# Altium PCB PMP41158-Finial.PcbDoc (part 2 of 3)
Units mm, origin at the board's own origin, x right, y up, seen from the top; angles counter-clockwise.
Board outline 125.73 x 87.63 mm, 6 copper layers (Top Layer, Layer 2, Layer 3, Layer 4, Layer 5, Bottom Layer), stack 1.999 mm thick; 200 components, 69 nets, 525 pads, 780 vias.
Unrouted connection lines stored in the file: 16.
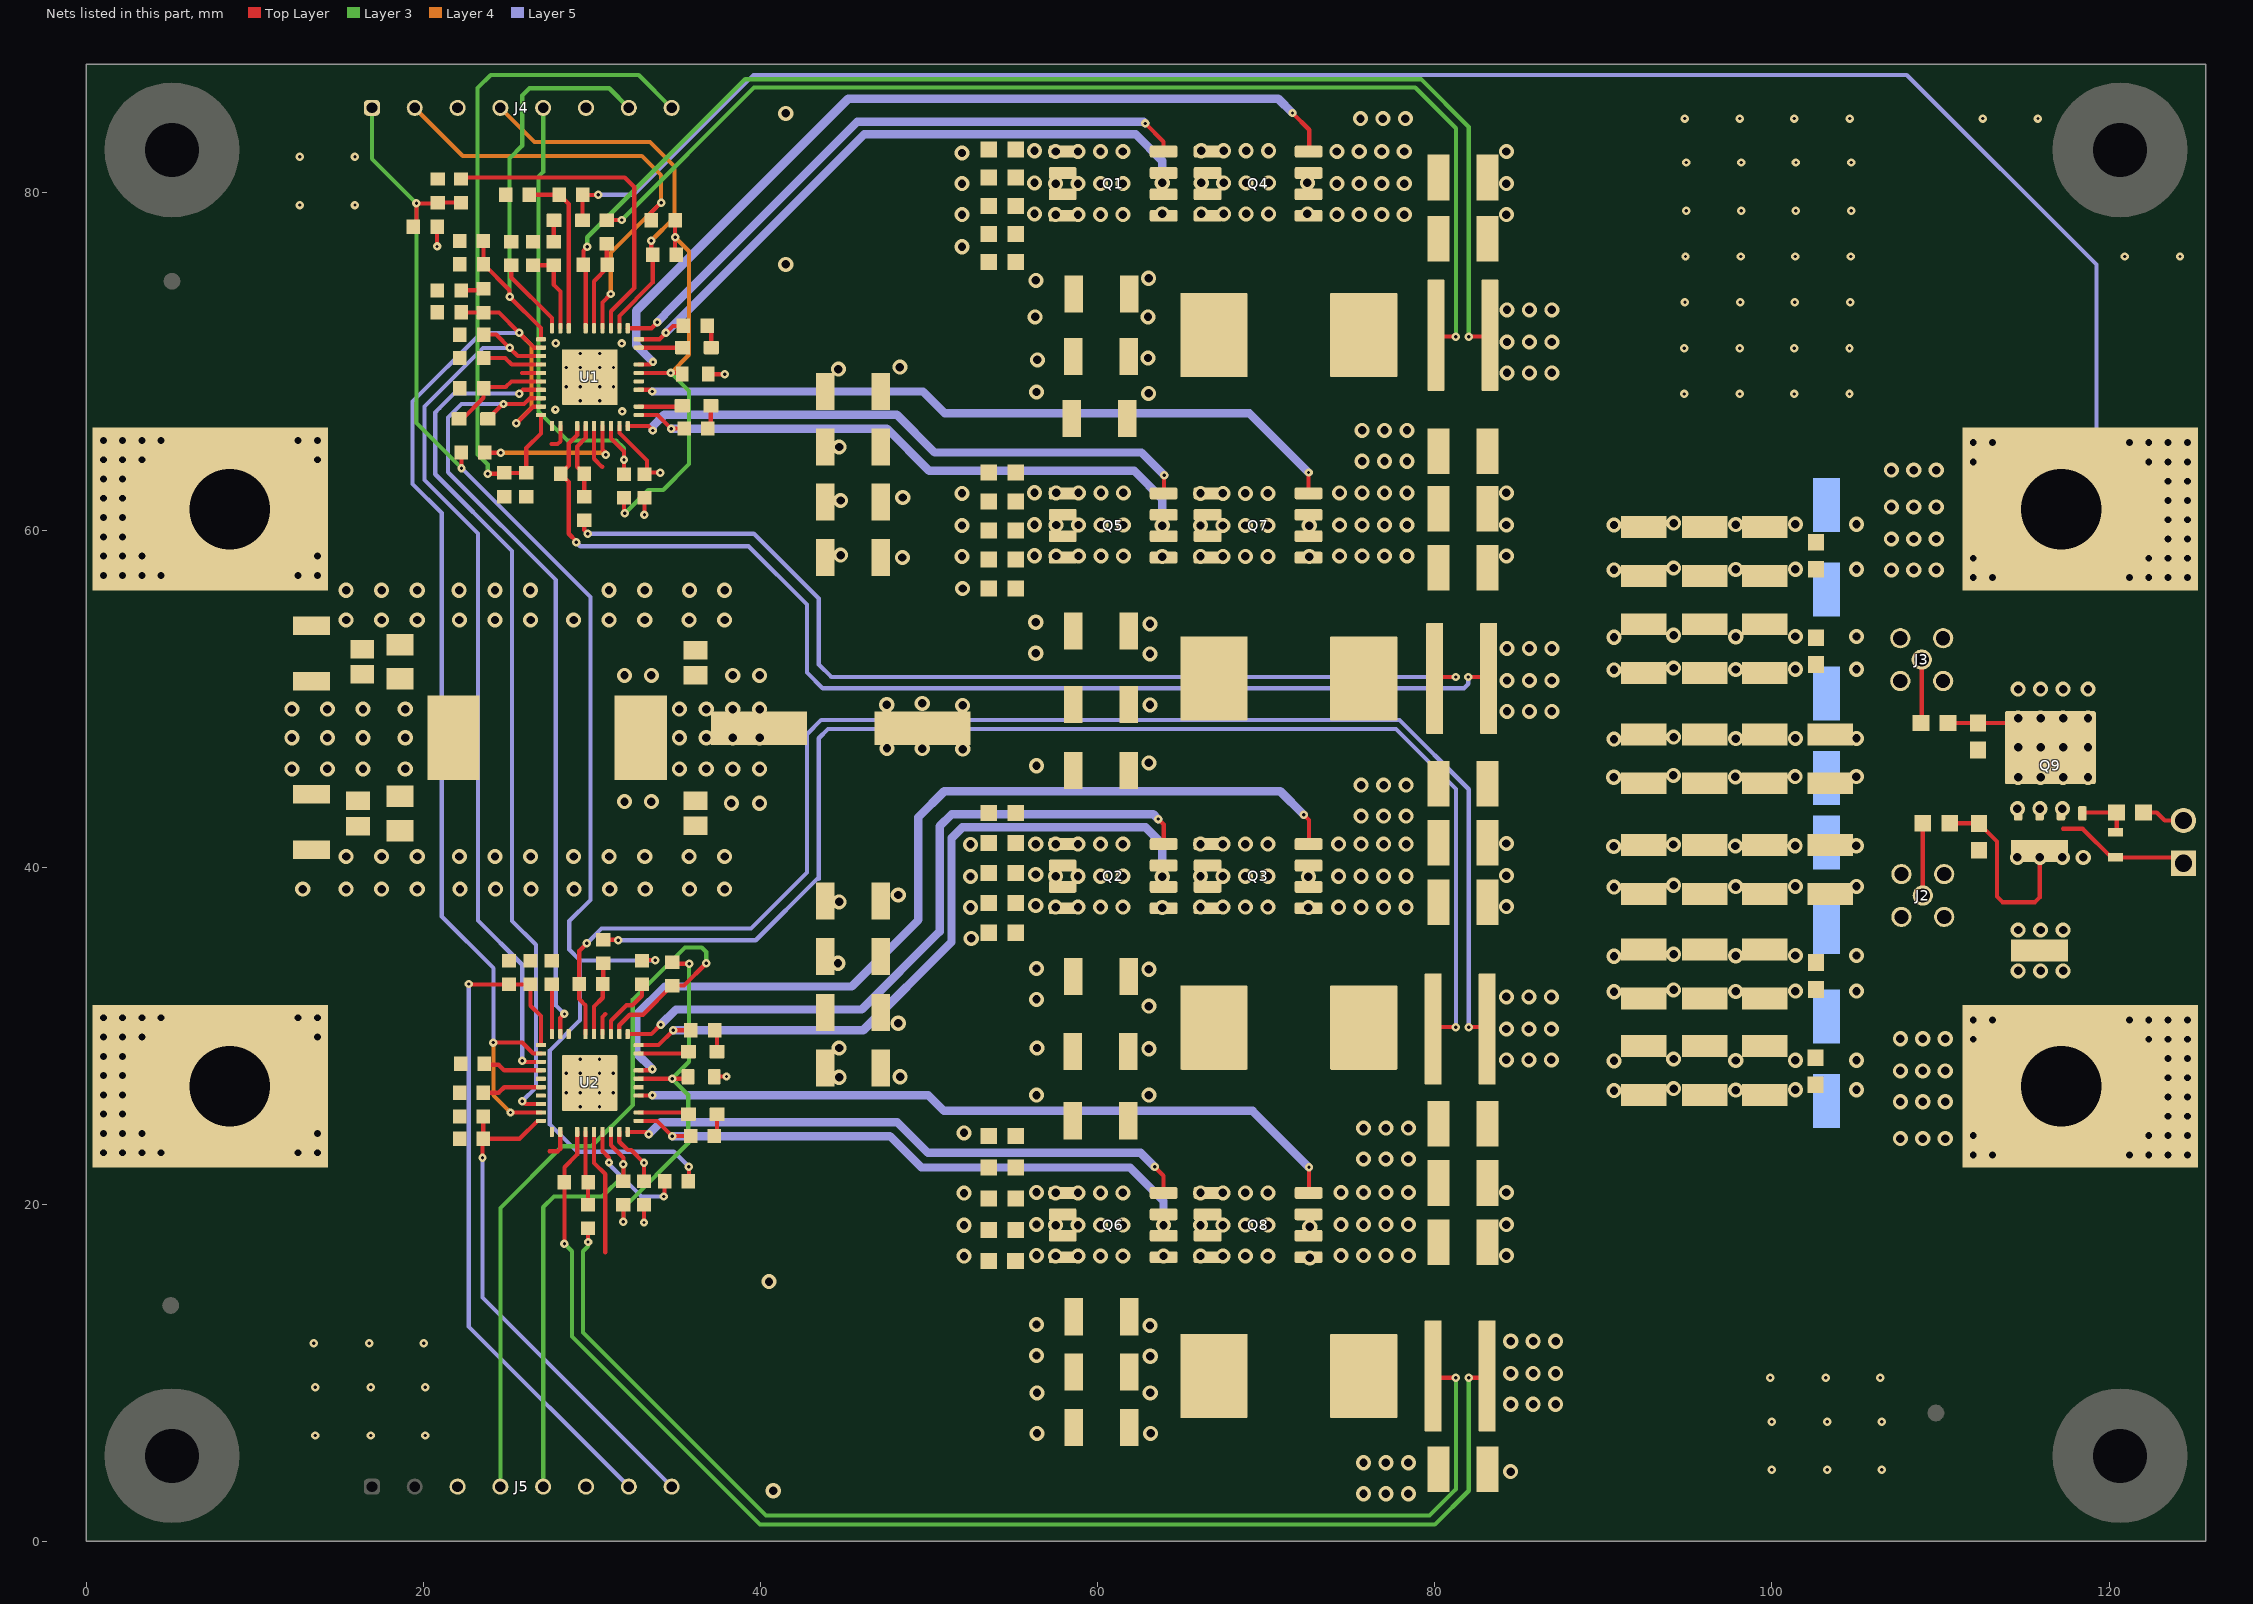
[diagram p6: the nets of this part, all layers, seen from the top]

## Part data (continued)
R46: library part CMP-0025686-1, "RES, 10.0 k, 0.1%, 0.1 W, AEC-Q200 Grade 1, 0603", Manufacturer=Vishay-Dale, Power_W=100mW, Supplier Part Number 1=TNP10.0KAACT-ND, TempCo="25 ppm/C", Tolerance_%=0.1%, Value2=0.1W, Value_Code=10k0, ValueDisplayed=10.0k
R47 R48: library part CMP-0022447-4, "RES, 49.9 k, 1%, 0.1 W, AEC-Q200 Grade 0, 0603", Manufacturer=Vishay-Dale, Power_W=100mW, Supplier Part Number 1=541-49.9KHCT-ND, TempCo="100 ppm/C", Tolerance_%=1%, Value2=0.1W, Value_Code=49k9, ValueDisplayed=49.9k
R49: library part CMP-0015418-2, "RES, 0.01, 1%, 3 W, 2512", Manufacturer=Bourns, Power_W=3W, Supplier Part Number 1=CRA2512-FZ-R010ELFCT-ND, TempCo="75 ppm/C", Tolerance_%=1%, Value_Code=R010, ValueDisplayed=0.01
T1 T2 T3 T4: library part CMP-0055442-1, "Terminal 50A Lug", Manufacturer=Panduit, Supplier Part Number 1=CB35-36-CY-ND, Voltage_V=600V
U1 U2: library part CMP-0122321-1, "Automotive, 4-V to 80-V, Functional Safety-Compliant, Dual Synchronous Buck Controller With Low IQ", Manufacturer="Texas Instruments", Max Supply Voltage=80V, Min Supply Voltage=4V, Nominal Supply Current=130uA, Operating Temperature Range="-40°C to +150°C", Output Voltage=0.8-60V, Switching Frequency=100-2200kHz
ZZ1: library part CMP-0003616-3
ZZ2: library part CMP-0077236-1
ZZ3: library part CMP-0077237-1
ZZ4: library part CMP-0077238-1

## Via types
v1: diameter 0.9, hole 0.5, Top Layer to Bottom Layer, 508 vias
v2: diameter 0.5, hole 0.2, Top Layer to Bottom Layer, 136 vias
v3: diameter 0.813, hole 0.406, Top Layer to Bottom Layer, 112 vias
v4: diameter 0.5, hole 0.2, Top Layer to Bottom Layer, tented both sides, 24 vias

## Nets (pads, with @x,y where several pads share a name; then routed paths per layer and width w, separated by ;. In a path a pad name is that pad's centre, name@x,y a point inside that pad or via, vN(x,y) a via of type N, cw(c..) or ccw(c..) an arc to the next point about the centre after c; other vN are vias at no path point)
EN1_1: R30.2 U1.20 | length 19.5
  Top Layer w0.25: R30.2@22.243,80.675 22.478,80.91 31.943,80.91 32.506,80.347 32.506,74.363 31.122,72.98 U1.20@31.122,71.973
EN1_2: R32.2 U2.20 | length 3.9
  Top Layer w0.25: U2.20@31.117,30.098 31.117,30.887 32.038,31.808 32.392,31.808 32.96,32.376 R32.2@32.96,33.044
EN2_1: R31.2 U1.6 | length 9
  Top Layer w0.25: R31.2@23.637,64.607 23.652,64.593 v2(24.579,64.593) ; U1.6@30.622,66.173 30.622,64.787 30.816,64.593 v2(30.816,64.46)
  Layer 4 w0.25: v2(24.579,64.593) 30.683,64.593 v2(30.816,64.46)
EN2_2: R33.2 U2.6 | length 7.1
  Top Layer w0.25: U2.6@30.617,24.298 30.617,23.154 31.006,22.765 v2@31.006,22.38 ; v2(34.26,20.463) 34.304,20.507 R33.2@34.304,21.378
  Layer 5 w0.25: v2@31.006,22.38 32.924,20.463 v2(34.26,20.463)
  other v2: 31.006,22.48
GND: C1.2 C2.2 C3.2 C4.2 C5.2 C6.2 C7.2 C8.2 C9.2 C10.2 C11.2 C12.2 C13.2 C14.2 C15.2 C16.2 C17.2 C18.2 C19.2 C20.2 C21.2 C22.2 C23.2 C24.2 C25.2 C26.2 C27.2 C28.2 C29.2 C30.2 C31.2 C32.2 C33.2 C34.2 C39.1 C40.1 C42.2 C43.2 C47.2 C49.2 C50.2 C51.2 C52.2 C53.2 C54.2 C55.2 C56.2 C57.2 C58.2 C59.2 C60.2 C61.2 C62.2 C63.2 C64.2 C65.2 C66.2 C67.2 C68.2 C69.2 C70.2 C71.2 C72.2 C73.2 C74.2 C77.2 C78.2 C79.2 C80.2 C81.2 C83.2 C84.2 C85.2 C86.2 C87.2 C88.2 C89.2 C90.2 C91.2 C92.2 C93.2 C94.2 C95.2 C96.2 C97.2 C98.2 C99.2 C100.2 C101.2 C102.2 C103.2 C104.2 C105.2 C106.2 C107.2 J2.2 J2.3 J2.4 J2.5 J3.2 J3.3 J3.4 J3.5 Q3.1 Q3.2 Q3.3 Q4.1 Q4.2 Q4.3 Q7.1 Q7.2 Q7.3 Q8.1 Q8.2 Q8.3 R49.1 T2.1 T4.1 U1.13 U1.37 U2.13 U2.37 | length 3.9
  Top Layer w0.25: v2(33.084,18.922) C43.2@33.084,19.968 ; v2(33.109,60.906) C42.2@33.109,61.916 ; C39.1@36.959,69.323 C39.1@36.9,69.264 36.926,69.239 v2(37.867,69.239) ; C40.1@37.247,27.568 37.263,27.584 v2(37.979,27.584)
  other v1: 75.768,2.831 77.101,2.831 78.433,2.831 40.75,3.012 75.768,4.666 77.101,4.666 78.433,4.666 63.137,6.413 63.118,8.809 63.118,10.991 63.101,12.809 40.5,15.414 72.584,16.824 52.067,16.925 74.435,16.959 75.768,16.959 77.101,16.959 78.433,16.959 72.584,18.659 52.067,18.76 74.435,18.794 75.768,18.794 77.101,18.794 78.433,18.794 52.067,20.665 74.435,20.699 75.768,20.699 77.101,20.699 78.433,20.699 75.768,22.688 77.101,22.688 78.433,22.688 107.617,23.901 108.95,23.901 110.283,23.901 52.067,24.239 75.768,24.523 77.101,24.523 78.433,24.523 107.617,26.082 108.95,26.082 110.283,26.082 63.037,26.48 44.656,27.537 107.617,27.917 108.95,27.917 110.283,27.917 90.63,28.507 97.849,28.534 101.395,28.55 105.015,28.55 94.168,28.62 63.037,29.233 44.656,29.275 107.617,29.822 108.95,29.822 110.283,29.822 63.037,31.757 90.63,32.608 97.849,32.635 101.395,32.651 105.015,32.651 94.168,32.722 114.606,33.851 115.939,33.851 117.272,33.851 63.037,33.949 44.591,34.3 52.5,35.779 114.606,36.276 115.939,36.276 117.272,36.276 72.502,37.602 52.452,37.615 74.294,37.627 75.627,37.627 76.96,37.627 78.292,37.627 44.656,37.941 12.841,38.697 15.409,38.697 17.519,38.697 19.629,38.697 22.167,38.697 24.277,38.697 26.387,38.697 28.937,38.697 31.047,38.697 33.157,38.697 35.791,38.697 37.867,38.697 52.452,39.45 72.502,39.437 74.294,39.462 75.627,39.462 76.96,39.462 78.292,39.462 15.409,40.634 17.519,40.634 19.629,40.634 22.134,40.634 24.244,40.634 26.354,40.634 28.904,40.634 31.014,40.634 33.124,40.634 35.757,40.634 37.867,40.634 90.612,41.232 97.831,41.259 101.377,41.275 104.997,41.275 52.452,41.355 94.15,41.346 74.294,41.367 75.627,41.367 76.96,41.367 78.292,41.367 75.627,43.034 76.96,43.034 78.292,43.034 75.627,44.869 76.96,44.869 78.292,44.869 90.612,45.334 97.831,45.361 101.377,45.377 104.997,45.377 94.15,45.447 63.037,46.186 51.993,47.006 47.5,47.052 49.589,47.034 51.981,49.596 47.489,49.642 63.101,49.629 49.589,49.715 63.101,52.651 90.63,53.643 97.849,53.67 101.395,53.686 105.015,53.686 94.168,53.756 63.101,54.433 15.409,54.666 17.519,54.666 19.629,54.666 22.134,54.666 24.244,54.666 26.354,54.666 28.904,54.666 31.014,54.666 33.124,54.666 35.757,54.666 37.867,54.666 15.409,56.434 17.519,56.434 19.629,56.434 22.116,56.434 24.244,56.434 26.347,56.434 31.006,56.434 33.124,56.434 35.791,56.434 37.866,56.434 51.981,56.534 90.63,57.637 97.849,57.664 101.395,57.68 105.015,57.68 94.168,57.75 72.55,58.427 51.949,58.436 74.35,58.464 75.682,58.464 77.015,58.464 78.348,58.464 44.749,58.518 51.949,60.271 72.55,60.262 74.35,60.299 75.682,60.299 77.015,60.299 78.348,60.299 44.749,61.754 51.949,62.176 74.35,62.204 75.682,62.204 77.015,62.204 78.348,62.204 75.682,64.082 77.015,64.082 78.348,64.082 44.656,64.929 75.682,65.917 77.015,65.917 78.348,65.917 63.021,68.105 44.613,69.551 62.983,70.209 62.983,72.645 63.021,74.941 41.495,75.759 51.949,76.805 51.949,78.718 74.187,78.718 75.52,78.718 76.853,78.718 78.186,78.718 72.441,78.759 51.949,80.553 74.187,80.553 75.52,80.553 76.853,80.553 78.186,80.553 72.441,80.594 51.949,82.372 74.187,82.458 75.52,82.458 76.853,82.458 78.186,82.458 75.59,84.415 76.922,84.415 78.255,84.415 41.495,84.719
  other v2: 99.997,4.25 103.279,4.25 106.513,4.25 13.589,6.283 16.871,6.283 20.105,6.283 13.59,9.143 16.871,9.143 20.105,9.143 99.908,9.716 103.19,9.716 106.424,9.716 13.5,11.75 16.782,11.75 20.016,11.75 31.795,67.038 27.829,67.15 94.804,68.076 98.086,68.076 101.32,68.076 104.602,68.076 31.764,71.073 27.856,71.094 94.839,73.512 98.12,73.512 101.354,73.512 104.636,73.512 120.925,76.23 124.207,76.23 94.907,78.948 98.189,78.948 101.423,78.948 104.705,78.948 12.653,79.283 15.935,79.283 12.654,82.143 15.935,82.143 94.818,84.415 98.1,84.415 101.334,84.415 104.616,84.415 112.5,84.415 115.782,84.415
  other v3: 111.943,22.936 113.086,22.936 121.214,22.936 122.357,22.936 123.5,22.936 124.643,22.936 1.007,23.063 2.15,23.063 3.293,23.063 4.436,23.063 12.564,23.063 13.707,23.063 111.943,24.079 122.357,24.079 123.5,24.079 124.643,24.079 1.007,24.206 2.15,24.206 3.293,24.206 13.707,24.206 123.5,25.222 124.643,25.222 1.007,25.349 2.15,25.349 123.5,26.365 124.643,26.365 1.007,26.492 2.15,26.492 123.5,27.508 124.643,27.508 1.007,27.635 2.15,27.635 123.5,28.651 124.643,28.651 1.007,28.778 2.15,28.778 111.943,29.794 122.357,29.794 123.5,29.794 124.643,29.794 1.007,29.921 2.15,29.921 3.293,29.921 13.707,29.921 111.943,30.937 113.086,30.937 121.214,30.937 122.357,30.937 123.5,30.937 124.643,30.937 1.007,31.064 2.15,31.064 3.293,31.064 4.436,31.064 12.564,31.064 13.707,31.064
  other v4: 29.292,25.798 30.442,25.798 28.467,26.623 29.292,26.623 30.442,26.623 31.267,26.623 28.467,27.773 29.292,27.773 30.442,27.773 31.267,27.773 29.292,28.598 30.442,28.598 29.297,67.673 30.447,67.673 28.472,68.498 29.297,68.498 30.447,68.498 31.272,68.498 28.472,69.648 29.297,69.648 30.447,69.648 31.272,69.648 29.297,70.473 30.447,70.473
HO1_1: Q1.4 U1.18 | length 37.9
  Top Layer w0.25: U1.18@32.122,71.973 33.534,71.973 v2@33.886,72.325 ; v2(62.826,84.124) 63.912,83.038 Q1.4@63.912,82.458
  Layer 5 w0.5: v2(33.877,72.334) 34.298,72.754 34.298,72.781 45.73,84.213 62.737,84.213 v2(62.826,84.124)
HO1_2: Q2.4 U2.18 | length 42.3
  Top Layer w0.25: U2.18@32.117,30.098 33.519,30.098 v2(34.071,30.65) ; v2(63.589,42.856) 63.919,42.525 63.919,41.379 Q2.4@63.912,41.372
  Layer 5 w0.5: v2(34.071,30.65) 34.98,31.559 46.004,31.559 50.625,36.18 50.625,42.427 51.345,43.148 63.297,43.148 v2(63.589,42.856)
HO2_1: Q5.4 U1.9 | length 35.1
  Top Layer w0.25: U1.9@32.122,66.173 33.349,66.173 v2(33.613,65.908) ; Q5.4@63.912,62.176 63.94,62.204 v2(63.94,63.262)
  Layer 5 w0.5: v2(33.613,65.908) 33.613,66.174 34.282,66.842 48.086,66.842 50.323,64.605 62.597,64.605 v2(63.94,63.262)
HO2_2: Q6.4 U2.9 | length 34.5
  Top Layer w0.25: U2.9@32.117,24.298 33.207,24.298 v2(33.355,24.149) ; v2(63.381,22.224) 63.912,21.694 Q6.4@63.912,20.674
  Layer 5 w0.5: v2(33.355,24.149) 34.087,24.881 48.101,24.881 49.932,23.05 62.556,23.05 v2(63.381,22.224)
IMON1_1: C108.2 J4.7 R8.1 U1.27 | length 26.5
  Top Layer w0.25: C108.2@23.556,75.775 R8.1@23.556,77.155 ; C108.2@23.562,75.775 25.108,74.229 v2(25.108,73.844) 26.972,71.98 U1.27@26.972,71.323
  Layer 3 w0.25: v2(25.108,73.844) 25.108,82.049 25.864,82.805 25.864,85.789 26.286,86.211 31.02,86.211 J4.7@32.182,85.05
IMON1_2: C109.2 J5.7 R9.1 U2.27 | length 41.3
  Top Layer w0.25: v2(22.682,33.069) 22.704,33.046 R9.1@25.077,33.046 C109.2@26.354,33.046 26.354,31.777 26.967,31.164 U2.27@26.967,29.448
  Layer 5 w0.25: v2(22.682,33.069) 22.682,12.749 J5.7@32.182,3.25
IMON2_1: C110.2 J4.8 R23.1 U1.36 | length 41.9
  Top Layer w0.25: v2(23.811,63.348) 24.756,63.348 R23.1@24.795,63.387 C110.2@26.098,63.387 26.098,64.864 26.972,65.738 U1.36@26.972,66.823
  Layer 3 w0.25: v2(23.811,63.348) 23.811,63.894 23.213,64.492 23.213,86.222 23.992,87 32.772,87 J4.8@34.722,85.05
IMON2_2: C111.2 J5.8 R24.1 U2.36 | length 30.5
  Top Layer w0.25: v2(23.5,22.764) 23.5,23.846 R24.1@23.545,23.892 ; C111.2@23.545,25.206 R24.1@23.545,23.892 ; U2.36@26.967,24.948 26.758,24.948 25.702,23.892 R24.1@23.545,23.892
  Layer 5 w0.25: v2(23.5,22.764) 23.5,14.472 J5.8@34.722,3.25
ISNS1+_1: C36.2 R6.1 U1.22 | length 5.3
  Top Layer w0.25: U1.22@30.122,71.973 30.122,74.766 30.897,75.541 30.897,75.548 30.872,75.573 R6.1@30.872,76.975
ISNS1+_2: C35.1 R7.1 U2.22 | length 4.4
  Top Layer w0.25: U2.22@30.117,30.098 30.117,31.73 30.639,32.252 C35.1@30.639,33.069 30.661,33.09 R7.1@30.661,34.3
ISNS2+_1: C75.2 R42.1 U1.4 | length 4.6
  Top Layer w0.25: R42.1@29.533,61.975 C75.2@29.533,63.348 29.122,63.758 29.122,64.967 29.622,65.467 U1.4@29.622,66.173
ISNS2+_2: C76.1 R43.1 U2.4 | length 4.4
  Top Layer w0.25: U2.4@29.617,24.298 29.617,21.448 C76.1@29.764,21.301 R43.1@29.764,19.986
LO1_1: Q4.4 U1.15 | length 51.4
  Top Layer w0.25: U1.15@32.772,69.823 v2@33.481,69.823 ; v2(71.554,84.746) 72.55,83.75 72.55,82.499 Q4.4@72.508,82.458
  Layer 5 w0.5: v2(33.616,69.975) 32.622,70.969 32.622,73.014 45.2,85.591 70.709,85.591 v2(71.554,84.746)
LO1_2: Q3.4 U2.15 | length 55.6
  Top Layer w0.25: U2.15@32.767,27.948 33.509,27.948 v2(33.584,28.023) ; v2(72.217,43.122) 72.533,42.805 72.533,41.397 Q3.4@72.508,41.372
  Layer 5 w0.5: v2(33.584,28.023) 32.617,28.99 32.617,31.217 34.321,32.921 45.41,32.921 49.364,36.875 49.364,42.973 50.898,44.508 70.83,44.508 v2(72.217,43.122)
LO2_1: Q7.4 U1.12 | length 42.9
  Top Layer w0.25: U1.12@32.772,68.323 v2@33.484,68.323 ; Q7.4@72.508,62.176 v2(72.508,63.418)
  Layer 5 w0.5: v2(33.567,68.222) 49.634,68.222 50.934,66.922 69.004,66.922 v2(72.508,63.418)
LO2_2: Q8.4 U2.12 | length 43.1
  Top Layer w0.25: U2.12@32.767,26.448 33.552,26.448 v2(33.584,26.48) ; Q8.4@72.508,20.674 72.533,20.699 v2(72.533,22.193)
  Layer 5 w0.5: v2(33.584,26.48) 49.942,26.48 50.883,25.539 69.188,25.539 v2(72.533,22.193)
NetC19_1: C19.1 C20.1 C21.1 C22.1 C23.1 C83.1 L1.1 T1.1
  other v1: 12.191,45.833 14.301,45.833 16.411,45.833 18.916,45.833 12.191,47.684 14.301,47.684 16.411,47.684 18.916,47.684 12.191,49.378 14.301,49.378 16.411,49.378 18.916,49.378
  other v3: 1.007,57.313 2.15,57.313 3.293,57.313 4.436,57.313 12.564,57.313 13.707,57.313 1.007,58.456 2.15,58.456 3.293,58.456 13.707,58.456 1.007,59.599 2.15,59.599 1.007,60.742 2.15,60.742 1.007,61.885 2.15,61.885 1.007,63.028 2.15,63.028 1.007,64.171 2.15,64.171 3.293,64.171 13.707,64.171 1.007,65.314 2.15,65.314 3.293,65.314 4.436,65.314 12.564,65.314 13.707,65.314
NetC37_1: C37.1 L2.1 Q1.1 Q1.2 Q1.3 Q4.5 Q4.6 Q4.7 Q4.8 U1.17 | length 39.3
  Top Layer w0.25: U1.17@32.772,71.323 34.007,71.323 34.797,72.113 C37.1@35.425,72.113
  Layer 5 w0.5: v2(34.385,71.718) 46.142,83.475 62.261,83.475 63.83,81.906 v1(63.83,80.594)
  other v1: 63.83,78.759 66.138,78.759 67.471,78.759 68.804,78.759 70.136,78.759 66.138,80.594 67.471,80.594 68.804,80.594 70.136,80.594 66.138,82.499 67.471,82.499 68.804,82.499 70.136,82.499
NetC37_2: C37.2 R10.2 | length 1.4
  Top Layer w0.25: C37.2@36.825,72.113 37.072,71.866 R10.2@37.072,70.831
NetC38_1: C38.1 L3.2 Q2.1 Q2.2 Q2.3 Q3.5 Q3.6 Q3.7 Q3.8 U2.17 | length 43.4
  Top Layer w0.25: U2.17@32.767,29.448 33.95,29.448 v2(34.828,30.325) C38.1@35.87,30.325
  Layer 5 w0.5: v2(34.828,30.325) 46.093,30.325 51.325,35.557 51.325,41.682 51.35,41.682 51.35,41.75 51.972,42.371 62.844,42.371 63.83,41.386 v1(63.83,39.437)
  other v1: 63.83,37.602 66.097,37.632 67.429,37.632 68.762,37.632 70.095,37.632 66.097,39.467 67.429,39.467 68.762,39.467 70.095,39.467 66.097,41.372 67.429,41.372 68.762,41.372 70.095,41.372
NetC38_2: C38.2 R11.2 | length 1.3
  Top Layer w0.25: C38.2@37.27,30.325 37.42,30.175 R11.2@37.42,29.064
NetC45_1: C45.1 L4.1 Q5.1 Q5.2 Q5.3 Q7.5 Q7.6 Q7.7 Q7.8 U1.10 | length 35.5
  Top Layer w0.25: U1.10@32.772,66.823 33.895,66.823 v2(34.695,66.023) C45.1@35.474,66.023
  Layer 5 w0.5: v2(34.695,66.023) 47.489,66.023 50.004,63.508 62.176,63.508 63.83,61.854 v1(63.83,60.262)
  other v1: 63.83,58.427 66.097,58.436 67.429,58.436 68.762,58.436 70.095,58.436 66.097,60.271 67.429,60.271 68.762,60.271 70.095,60.271 66.097,62.176 67.429,62.176 68.762,62.176 70.095,62.176
NetC45_2: C45.2 R15.2 | length 1.4
  Top Layer w0.25: C45.2@36.874,66.023 37.049,66.198 R15.2@37.049,67.372
NetC46_1: C46.1 L5.2 Q6.1 Q6.2 Q6.3 Q8.5 Q8.6 Q8.7 Q8.8 U2.10 | length 35.6
  Top Layer w0.25: U2.10@32.767,24.948 33.851,24.948 v2(34.75,24.049) C46.1@35.843,24.049
  Layer 5 w0.5: v2(34.75,24.049) 47.672,24.049 49.538,22.183 61.922,22.183 63.901,20.204 v1(63.901,18.769)
  other v1: 63.901,16.934 66.097,16.934 67.429,16.934 68.762,16.934 70.095,16.934 66.097,18.769 67.429,18.769 68.762,18.769 70.095,18.769 66.097,20.674 67.429,20.674 68.762,20.674 70.095,20.674
NetC46_2: C46.2 R16.2 | length 1.4
  Top Layer w0.25: C46.2@37.243,24.049 37.42,24.226 R16.2@37.42,25.347
NetC47_1: C47.1 J1.1 Q9.1 Q9.2 Q9.3 R46.1 R47.1 R49.2 | length 19.4
  Top Layer w0.25: R47.1@110.546,42.608 112.268,42.608 C47.1@112.273,42.603 113.354,41.522 113.354,38.259 113.686,37.927 115.6,37.927 115.882,38.209 v1@115.882,40.279 ; 117.272,42.276 118.439,42.276 120.138,40.578 R46.1@120.386,40.578 124.063,40.578 J1.1@124.411,40.23
  other v1: 114.565,40.578 115.897,40.578 117.23,40.578 118.472,40.578 114.565,43.467 115.897,43.467 117.23,43.467
NetC48_1: C48.1 R14.1 | length 1.2
  Top Layer w0.25: C48.1@22.306,74.229 R14.1@23.548,74.229
NetC82_1: C82.1 R14.2 U1.28 U1.35 U2.28 U2.35 | length 71
  Top Layer w0.25: C82.1@22.232,72.93 22.257,72.905 R14.2@23.56,72.905 24.476,72.905 v2(25.684,71.697) 26.558,70.823 U1.28@26.972,70.823 ; v2(24.148,29.598) 25.86,29.598 26.51,28.948 U2.28@26.967,28.948 ; v2(25.165,25.448) U2.35@26.967,25.448 ; v2(25.505,66.348) 25.552,66.348 26.527,67.323 U1.35@26.972,67.323
  Layer 4 w0.25: v2(24.148,29.598) 24.148,26.465 v2(25.165,25.448) ; v2(25.505,66.348) 26.413,67.255 26.413,70.968 v2(25.684,71.697)
  Layer 5 w0.25: v2(24.148,29.598) 24.148,34.009 21.084,37.073 21.084,61.01 19.356,62.738 19.356,67.622 23.431,71.697 v2(25.684,71.697)
NetJ1_2: J1.2 R12.1 | length 2.6
  Top Layer w0.25: R12.1@122.05,43.25 122.826,43.25 123.306,42.77 J1.2@124.411,42.77
NetJ2_1: J2.1 R47.2 | length 4.3
  Top Layer w0.25: R47.2@108.946,42.608 108.946,38.325 J2.1@108.95,38.321
NetJ3_1: J3.1 R48.1 | length 3.8
  Top Layer w0.25: R48.1@108.85,48.549 108.886,48.586 J3.1@108.886,52.316
NetJ4_1: J4.1 R22.1 R30.1 R31.1 R32.1 R33.1 R34.2 | length 87.7
  Top Layer w0.25: R22.1@19.405,78 19.584,78.179 v2(19.584,79.382) 20.796,79.382 R34.2@20.843,79.429 R30.1@22.231,79.429 ; R31.1@22.237,64.607 22.257,64.587 v2(22.257,63.673) ; R32.1@32.76,34.49 v2@33.552,34.49 ; R33.1@35.704,21.378 35.749,21.423 v2(35.749,22.227)
  Layer 3 w0.25: J4.1@16.942,85.05 16.942,82.025 v2(19.584,79.382) 19.584,66.346 v2(22.257,63.673)
  Layer 5 w0.25: v2(22.257,63.673) 29.903,56.027 29.903,38.055 28.649,36.802 28.649,35.109 29.29,34.469 ; v2(33.752,34.49) 33.73,34.469 29.29,34.469 ; v2(35.749,22.227) 34.851,23.125 29.103,23.125 27.496,24.732 27.496,29.132 29.29,30.926 29.29,34.469
NetL2_2: L2.2 R4.1 R6.2 | length 68.3
  Top Layer w0.25: R6.2@30.872,78.375 30.895,78.398 v2(31.764,78.398) ; R4.1@79.988,71.478 v2(81.25,71.478)
  Layer 3 w0.25: v2(31.764,78.398) 39.616,86.25 78.842,86.25 81.25,83.842 v2(81.25,71.478)
NetL3_1: L3.1 R5.2 R7.2 | length 77.6
  Top Layer w0.25: R7.2@30.661,35.7 31.528,35.7 v2(31.565,35.664) ; R5.2@79.9,30.514 v2(81.25,30.514)
  Layer 5 w0.25: v2(31.565,35.664) 39.713,35.664 43.35,39.3 43.448,39.3 43.448,47.654 43.999,48.205 77.691,48.205 81.25,44.646 v2(81.25,30.514)
NetL4_2: L4.2 R40.1 R42.2 | length 59.3
  Top Layer w0.25: R42.2@29.533,60.575 29.533,60.01 29.743,59.799 v2(29.743,59.782) ; R40.1@80.076,51.275 v2@81.233,51.275
  Layer 5 w0.25: v2(29.743,59.782) 39.601,59.782 43.448,55.934 43.448,52.033 44.196,51.285 v2(81.233,51.285)
NetL5_1: L5.1 R41.2 R43.2 | length 71.2
  Top Layer w0.25: v2(29.764,17.763) R43.2@29.764,18.586 ; R41.2@79.9,9.705 v2(81.25,9.705)
  Layer 3 w0.25: v2(29.764,17.763) 29.764,17.515 29.467,17.218 29.467,12.394 40.322,1.539 79.689,1.539 81.25,3.1 v2(81.25,9.705)
NetQ9_4: Q9.4 R12.2 R46.2 | length 3.3
  Top Layer w0.25: Q9.4@118.416,43.194 118.472,43.25 R12.2@120.45,43.25 120.45,42.141 R46.2@120.386,42.078
NetR1_1: R1.1 R13.2 | length 1.2
  Top Layer w0.25: R13.2@27.724,77.162 27.724,78.359 R1.1@27.741,78.375
NetR2_1: R2.1 R3.2 U1.24 | length 9.9
  Top Layer w0.25: R3.2@26.276,79.899 R2.1@28.035,79.899 ; R2.1@28.061,79.899 28.622,79.339 U1.24@28.622,71.973
NetR10_1: R10.1 U1.16 | length 2.6
  Top Layer w0.25: U1.16@32.772,70.823 35.363,70.823 R10.1@35.372,70.831
NetR11_1: R11.1 U2.16 | length 3
  Top Layer w0.25: U2.16@32.767,28.948 35.604,28.948 R11.1@35.72,29.064
NetR13_1: R13.1 R50.2 U1.25 | length 5.2
  Top Layer w0.25: R50.2@26.495,75.712 27.674,75.712 27.724,75.762 27.724,74.559 28.122,74.161 U1.25@28.122,71.973
NetR15_1: R15.1 U1.11 | length 2.6
  Top Layer w0.25: U1.11@32.772,67.323 35.3,67.323 R15.1@35.349,67.372
NetR16_1: R16.1 U2.11 | length 3
  Top Layer w0.25: U2.11@32.767,25.448 35.619,25.448 R16.1@35.72,25.347
NetR17_2: R17.2 U1.26 | length 4.8
  Top Layer w0.25: R17.2@25.203,75.723 25.203,74.999 27.622,72.58 U1.26@27.622,71.973
NetR18_2: R18.2 U1.29 U2.29 | length 52.8
  Top Layer w0.25: R18.2@23.566,71.597 24.319,71.597 v2(25.108,70.808) 25.594,70.323 U1.29@26.972,70.323 ; v2(25.86,28.523) 25.935,28.448 U2.29@26.967,28.448
  Layer 5 w0.25: v2(25.108,70.808) 23.532,70.808 20.056,67.333 20.056,62.971 23.231,59.796 23.231,36.839 25.86,34.21 v2(25.86,28.523)
NetR19_2: R19.2 U1.30 | length 3.6
  Top Layer w0.25: R19.2@23.566,70.214 24.846,70.214 25.238,69.823 U1.30@26.972,69.823
NetR20_2: R20.2 U2.26 | length 2.9
  Top Layer w0.25: U2.26@27.617,30.098 R20.2@27.617,33.046
NetR21_2: R21.2 U2.30 | length 3.5
  Top Layer w0.25: R21.2@23.617,28.348 23.689,28.275 24.464,28.275 24.791,27.948 U2.30@26.967,27.948
NetU1_33: U1.33 U2.34 | length 51.7
  Top Layer w0.25: v2(25.684,68.099) 25.908,68.323 U1.33@26.972,68.323 ; v2(25.86,26.12) 26.032,25.948 U2.34@26.967,25.948
  Layer 5 w0.25: v2(25.684,68.099) 21.813,68.099 20.932,67.217 20.932,67.215 20.698,66.981 20.698,63.315 25.256,58.756 25.256,36.816 26.672,35.401 26.672,26.932 v2(25.86,26.12)
nFAULT1_1: J4.4 R26.1 U1.19 | length 22.8
  Top Layer w0.25: U1.19@31.622,71.973 31.622,72.709 33.598,74.685 R26.1@33.598,76.341 33.516,76.423 v2(33.516,77.167)
  Layer 4 w0.25: J4.4@24.562,85.05 26.59,83.021 33.442,83.021 34.889,81.575 34.889,78.539 v2(33.516,77.167)
nFAULT1_2: J5.4 R28.1 U2.19 | length 46.5
  Top Layer w0.25: 31.617,30.439 31.617,30.621 32.24,31.245 33.02,31.245 R28.1@34.75,32.975 35.455,32.975 v2(36.779,34.3)
  Layer 3 w0.25: J5.4@24.562,3.25 24.562,19.79 28.22,23.448 29.978,23.448 32.42,25.89 32.42,32.148 35.516,35.244 36.506,35.244 36.779,34.971 v2(36.779,34.3)
nFAULT2_1: J4.5 R27.1 U1.7 | length 28
  Top Layer w0.25: U1.7@31.122,66.173 31.122,65.444 31.895,64.671 v2(31.895,64.177) R27.1@31.895,63.316
  Layer 3 w0.25: J4.5@27.102,85.05 27.102,81.24 26.822,80.96 26.822,67.031 28.539,65.314 31.432,65.314 31.895,64.851 v2(31.895,64.177)
nFAULT2_2: J5.5 R29.1 U2.7 | length 26
  Top Layer w0.25: U2.7@31.117,24.298 31.117,23.505 31.859,22.764 v2(31.859,22.38) R29.1@31.859,21.368
  Layer 3 w0.25: J5.5@27.102,3.25 27.102,19.822 27.742,20.463 30.603,20.463 31.859,21.719 v2(31.859,22.38)
PFM_SYNC: R35.2 U1.34 U2.25 | length 46.8
  Top Layer w0.25: R35.2@23.816,66.591 24.706,67.481 v2(24.747,67.481) 25.97,67.481 26.312,67.823 U1.34@26.972,67.823 ; U2.25@28.117,30.098 28.117,31.047 v2(28.364,31.294)
  Layer 5 w0.25: v2(24.747,67.481) 22.256,67.481 21.461,66.685 21.461,63.43 27.853,57.038 27.853,31.805 v2(28.364,31.294)
PG1_1: J4.2 R25.1 U1.21 | length 28.1
  Top Layer w0.25: U1.21@30.622,71.973 30.622,73.504 v2@31.113,73.995 ; R25.1@33.527,78.375 33.527,78.857 v2(34.099,79.429)
  Layer 4 w0.25: J4.2@19.482,85.05 22.332,82.2 32.955,82.2 34.099,81.056 v2(34.099,79.429) 31.105,76.434 v2(31.105,74.004)
PG1_2: C41.2 C44.2 C48.2 C82.2 C108.1 C109.1 C110.1 C111.1 J4.3 J4.6 J5.3 J5.6 R3.1 R8.2 R9.2 R17.1 R18.1 R19.1 R20.1 R21.1 R23.2 R24.2 R34.1 R50.1 U1.1 U1.2 U1.5 U1.31 U2.1 U2.2 U2.5 U2.21 U2.24 U2.31 | length 15.6
  Top Layer w0.25: 25.842,69.323 U1.31@26.972,69.323 ; 27.475,23.154 27.982,23.154 28.117,23.289 U2.2@28.117,24.298 ; 27.595,65.099 27.955,65.099 28.122,65.266 U1.2@28.122,66.173 ; U2.5@30.117,24.298 30.117,22.457 30.79,21.784 30.79,17.162 ; U1.5@30.122,66.173 30.122,64.232 30.602,63.752 ; U2.21@30.617,30.098 30.617,31.121 30.79,31.294
SYNCOUT: U2.33
VCCA: C39.2 R25.2 R26.2 R27.2 U1.14 | length 25.3
  Top Layer w0.25: R27.2@31.895,61.916 31.895,61.05 v2(31.946,60.999) ; U1.14@32.772,69.323 v2(34.677,69.323) 35.292,69.323 C39.2@35.35,69.264 ; R25.2@34.927,78.375 v2(34.927,77.373) 34.927,76.412 R26.2@34.998,76.341
  Layer 3 w0.25: v2(31.946,60.999) 33.329,62.383 34.227,62.383 35.757,63.912 35.757,68.243 v2(34.677,69.323)
  Layer 4 w0.25: v2(34.677,69.323) 35.757,70.402 35.757,76.543 v2(34.927,77.373)
VCCB: C40.2 R28.2 R29.2 U2.14 | length 22.8
  Top Layer w0.25: v2(31.859,18.961) R29.2@31.859,19.968 ; U2.14@32.767,27.448 v2(34.75,27.448) 35.576,27.448 C40.2@35.697,27.568 ; R28.2@34.75,34.375 34.85,34.276 v2(35.757,34.276)
  Layer 3 w0.25: v2(31.859,18.961) 31.859,19.777 35.711,23.629 35.711,26.487 v2(34.75,27.448) 35.757,28.455 v2(35.757,34.276)
VDDA: C41.1 R35.1 U1.32 | length 6.1
  Top Layer w0.25: R35.1@22.116,66.591 22.307,66.591 23.566,67.85 C41.1@23.566,68.412 23.634,68.48 24.876,68.48 25.219,68.823 U1.32@26.972,68.823
VDDB: C44.1 U2.32 | length 3.6
  Top Layer w0.25: C44.1@23.545,26.623 24.466,26.623 24.791,26.948 U2.32@26.967,26.948
VIN: C1.1 C2.1 C3.1 C4.1 C5.1 C6.1 C7.1 C8.1 C9.1 C10.1 C11.1 C12.1 C13.1 C14.1 C15.1 C16.1 C17.1 C18.1 C24.1 C25.1 C26.1 C42.1 C43.1 C49.1 C50.1 C51.1 C52.1 C53.1 C54.1 C55.1 C56.1 C57.1 C58.1 C59.1 C60.1 C61.1 C62.1 C63.1 C64.1 C65.1 C66.1 C77.1 C78.1 C79.1 C80.1 L1.2 Q1.5 Q1.6 Q1.7 Q1.8 Q2.5 Q2.6 Q2.7 Q2.8 Q5.5 Q5.6 Q5.7 Q5.8 Q6.5 Q6.6 Q6.7 Q6.8 R22.2 U1.8 U2.8 | length 9.2
  Top Layer w0.25: v2(20.806,76.827) R22.2@20.805,78 ; U2.8@31.617,24.298 31.617,23.714 32.117,23.214 32.327,23.214 v2(33.084,22.458) C43.1@33.084,21.368 ; U1.8@31.622,66.173 31.622,65.764 33.259,64.126 33.259,63.316 33.352,63.409 v2(34.044,63.409)
  other v1: 56.4,6.413 56.4,8.809 56.368,11.033 56.368,12.868 57.5,16.934 58.833,16.934 60.165,16.934 61.498,16.934 56.368,16.967 57.5,18.769 58.833,18.769 60.165,18.769 61.498,18.769 56.368,18.802 57.5,20.674 58.833,20.674 60.165,20.674 61.498,20.674 56.368,20.707 56.368,26.48 48.277,27.568 56.4,29.275 48.163,30.74 56.368,32.156 56.368,33.991 57.5,37.632 58.833,37.632 60.165,37.632 61.498,37.632 56.32,37.731 48.163,38.35 57.5,39.467 58.833,39.467 60.165,39.467 61.498,39.467 56.32,39.566 56.32,41.367 57.5,41.372 58.833,41.372 60.165,41.372 61.498,41.372 38.265,43.798 39.938,43.798 31.925,43.894 33.519,43.894 35.185,45.833 36.779,45.833 38.344,45.833 39.938,45.833 56.368,46.015 35.185,47.684 36.779,47.684 38.344,47.684 39.938,47.684 35.185,49.378 36.779,49.378 38.344,49.378 39.938,49.378 31.925,51.378 33.519,51.378 38.344,51.378 39.938,51.378 56.32,52.692 56.32,54.527 48.414,58.372 56.25,58.477 57.529,58.464 58.861,58.464 60.194,58.464 61.527,58.464 56.25,60.312 57.529,60.299 58.861,60.299 60.194,60.299 61.527,60.299 48.433,61.933 56.25,62.217 57.529,62.204 58.861,62.204 60.194,62.204 61.527,62.204 56.368,68.191 48.261,69.667 56.421,70.098 56.282,72.645 56.336,74.811 57.5,78.718 58.833,78.718 60.165,78.718 61.498,78.718 56.25,78.759 57.5,80.553 58.833,80.553 60.165,80.553 61.498,80.553 56.25,80.594 57.5,82.458 58.833,82.458 60.165,82.458 61.498,82.458 56.25,82.499
VOUT1_1: C27.1 C28.1 C29.1 C30.1 C31.1 C32.1 C33.1 C34.1 C35.2 C36.1 C67.1 C68.1 C69.1 C70.1 C71.1 C72.1 C73.1 C74.1 C75.1 C76.2 C81.1 C84.1 C85.1 C86.1 C87.1 C88.1 C89.1 C90.1 C91.1 C92.1 C93.1 C94.1 C95.1 C96.1 C97.1 C98.1 C99.1 C100.1 C101.1 C102.1 C103.1 C104.1 C105.1 C106.1 C107.1 Q9.5 Q9.6 Q9.7 Q9.8 Q9.9@116.511,47.094 R1.2 R2.2 R4.2 R5.1 R40.2 R41.1 R48.2 T3.1 U1.3 U1.23 U2.3 U2.23 | length 428.1
  Top Layer w0.25: v2(28.364,17.662) C76.2@28.364,21.301 28.364,22.202 29.117,22.955 U2.3@29.117,24.298 ; v2@29.079,59.325 28.622,59.782 28.622,62.858 C75.1@28.133,63.348 28.622,63.837 28.622,65.143 29.122,65.643 U1.3@29.122,66.173 ; C35.2@29.239,33.069 29.239,35.037 v2(29.692,35.49) ; C35.2@29.292,33.069 29.292,32.679 29.239,32.626 29.239,32.184 29.617,31.805 U2.23@29.617,30.098 ; R1.2@29.441,78.375 R2.2@29.441,79.879 ; R2.2@29.461,79.899 R2.2@29.441,79.879 ; U1.23@29.622,71.973 29.622,75.423 29.497,75.548 29.497,76.569 v2@29.733,76.805 ; v2(30.376,79.899) 29.462,79.879 R2.2@29.441,79.879 ; v2(82.01,9.705) R41.1@83.1,9.705 ; v2(82.01,30.514) R5.1@83.1,30.514 ; v2@82.01,51.275 R40.2@83.276,51.275 ; v2(82.01,71.478) R4.2@83.188,71.478 ; R48.2@110.45,48.549 C81.1@112.22,48.549 115.057,48.549 Q9.9@116.511,47.094
  Layer 3 w0.25: v2(28.364,17.662) 28.812,17.214 28.812,12.15 39.962,1 80,1 82.01,3.01 v2(82.01,9.705) ; v2(29.715,76.805) 29.715,77.373 39.092,86.75 79.176,86.75 82.01,83.916 v2(82.01,71.478)
  Layer 5 w0.25: v2(29.061,59.281) 29.302,59.04 39.288,59.04 42.75,55.578 42.75,51.552 43.682,50.62 81.724,50.62 81.983,50.878 v2(81.983,51.285) ; v2(29.692,35.49) 30.566,36.365 39.428,36.365 42.75,39.687 42.75,47.886 43.592,48.728 77.905,48.728 82.01,44.624 v2(82.01,30.514) ; v2(30.376,79.899) 32.481,79.899 39.582,87 108,87 119.25,75.75 119.25,65.35 T3.1@117.15,63.25
  other v1: 84.499,4.14 84.5,8.137 85.833,8.137 87.165,8.137 84.5,9.972 85.833,9.972 87.165,9.972 84.5,11.877 85.833,11.877 87.165,11.877 84.25,16.959 84.25,18.794 84.25,20.699 90.63,26.75 97.849,26.777 101.395,26.793 105.015,26.793 94.168,26.863 84.25,28.565 85.583,28.565 86.915,28.565 84.25,30.4 85.583,30.4 86.915,30.4 84.25,32.305 85.583,32.305 86.915,32.305 90.63,34.718 97.849,34.745 101.395,34.762 105.015,34.762 94.168,34.832 84.25,37.665 90.63,38.82 97.849,38.847 101.395,38.863 105.015,38.863 94.168,38.933 84.25,39.5 84.25,41.405 114.606,45.334 115.939,45.334 117.272,45.334 118.75,45.334 114.606,47.111 115.939,47.111 117.272,47.111 118.75,47.111 90.63,47.602 97.849,47.629 101.395,47.645 105.015,47.645 94.168,47.715 114.606,48.834 115.939,48.834 117.272,48.834 118.75,48.834 84.28,49.24 85.613,49.24 86.945,49.24 114.606,50.566 115.939,50.566 117.272,50.566 118.75,50.566 84.28,51.075 85.613,51.075 86.945,51.075 90.63,51.703 97.849,51.73 101.395,51.746 105.015,51.746 94.168,51.816 84.28,52.98 85.613,52.98 86.945,52.98 107.085,57.637 108.417,57.637 109.75,57.637 84.25,58.464 107.085,59.472 108.417,59.472 109.75,59.472 84.25,60.299 90.63,60.299 97.849,60.326 101.395,60.343 105.015,60.343 94.168,60.413 107.085,61.377 108.417,61.377 109.75,61.377 84.25,62.204 107.085,63.558 108.417,63.558 109.75,63.558 84.28,69.322 85.613,69.322 86.945,69.322 84.28,71.157 85.613,71.157 86.945,71.157 84.28,73.062 85.613,73.062 86.945,73.062 84.25,78.718 84.25,80.553 84.25,82.458
  other v2: 99.998,7.109 103.28,7.109 106.514,7.109 94.804,70.794 98.086,70.794 101.32,70.794 104.602,70.794 94.873,76.23 98.155,76.23 101.389,76.23 104.671,76.23 94.908,81.808 98.19,81.808 101.424,81.808 104.706,81.808
  other v3: 111.943,57.186 113.086,57.186 121.214,57.186 122.357,57.186 123.5,57.186 124.643,57.186 111.943,58.329 122.357,58.329 123.5,58.329 124.643,58.329 123.5,59.472 124.643,59.472 123.5,60.615 124.643,60.615 123.5,61.758 124.643,61.758 123.5,62.901 124.643,62.901 111.943,64.044 122.357,64.044 123.5,64.044 124.643,64.044 111.943,65.187 113.086,65.187 121.214,65.187 122.357,65.187 123.5,65.187 124.643,65.187
pads on no net: FID1.1 FID2.1 FID3.1 H1.1 H2.1 H3.1 H4.1 H5.0 H6.0 H7.0 H8.0 J5.1 J5.2 LBL1.0 Q9.9@114.139,45.184 Q9.9@115.181,45.479 Q9.9@115.181,46.629 Q9.9@115.181,47.779 Q9.9@116.511,45.479 Q9.9@116.511,46.629 Q9.9@116.511,46.764 Q9.9@116.511,47.779 Q9.9@117.841,45.479 Q9.9@117.841,46.629 Q9.9@117.841,47.779 Q9.9@118.884,45.184

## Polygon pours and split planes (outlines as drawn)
GND on Top Layer "TOP_LAYER_GND_P052" (solid, remove dead copper, pour order 52): 115.25,36.816 115.015,37.051 114.688,37.051 114.126,37.051 113.624,36.549 113.624,32.029 107.511,32.029 106.911,31.429 106.911,23.298 107.959,22.25 125.219,22.25 125.219,36.444 124.178,37.541 116.63,37.541 116.511,37.423 116.511,36.287 116,36.287 116,37.374 115.72,37.655 113.494,37.655 112.966,38.183 112.966,46.171 112.911,46.226 112.911,47.978 111,49.889 111,53.838 110.7,54.138 107.466,54.138 106.911,53.582 106.911,32.89 107.472,32.329 113.423,32.329 113.423,36.861 113.812,37.25 115.6,37.25 115.667,37.183 115.667,36.287 115.25,36.287
GND on Top Layer "TOP_LAYER_GND_P058" (solid, remove dead copper, pour order 58): 43.977,86.5 45.25,85.227 45.25,58.076 39.648,52.474 12.652,52.474 11.736,53.39 11.736,55.799 13.687,57.75 37.501,57.75 39.667,59.915 39.667,85.376 40.791,86.5 43.25,86.5
GND on Top Layer "TOP_LAYER_GND_P057" (solid, remove dead copper, pour order 57): 51.118,24.337 51.836,25.055 53.868,25.055 54.118,24.805 54.118,15.985 53.75,15.618 51.856,15.618 51.118,16.356
VIN on Top Layer "TOP_LAYER_VIN_P000" (solid, remove dead copper, pour order 0): 46.992,86.567 45.5,85.075 45.5,57.779 39.667,51.946 39.667,43.785 45.5,37.952 45.5,2.294 47.044,0.75 58.722,0.75 60.133,2.162 60.133,14.208 62.572,16.647 62.572,21.564 60.133,24.003 60.133,34.696 62.572,37.135 62.572,41.809 60.104,44.276 60.104,55.558 62.572,58.025 62.572,62.547 60.104,65.014 60.104,75.175 62.572,77.643 62.572,84.772 60.777,86.567
GND on Top Layer "TOP_LAYER_GND_P054" (solid, remove dead copper, pour order 54): 51,83.66 51.718,84.379 53.75,84.379 54,84.129 54,75.309 53.633,74.941 51.738,74.941 51,75.679
GND on Top Layer "TOP_LAYER_GND_P002" (solid, remove dead copper, pour order 2): 71.7,85.317 72.949,86.567 79.612,86.567 80.864,85.314 80.864,75.812 80.683,75.631 73.183,75.631 71.7,77.113 71.7,79.349
PG1_2 on Top Layer "TOP_LAYER_PG1_2_P026" (solid, remove dead copper, pour order 26): 35.532,78.98 31.601,78.98 30.057,80.524 25.676,80.524 25.676,79.274 27.105,77.845 27.105,76.817 26.852,76.569 23.378,76.569 22.775,75.966 22.775,69.738 22.924,69.589 27.25,69.589 27.25,69.073 22.946,69.073 22.775,68.902 22.775,67.595 21.637,66.457 21.637,64.313 23.163,62.787 26.723,62.787 26.723,65.86 27.303,66.441 27.745,66.441 27.745,64.171 30.798,64.171 31.243,63.725 31.243,58.598 30.797,58.152 16.257,58.152 15,59.409 15,85.438 16.062,86.5 35.321,86.5 36,85.821 36,79.448
PG1_2 on Top Layer "TOP_LAYER_PG1_2_P043" (solid, remove dead copper, pour order 43): 35.588,17.986 36.667,16.906 36.667,2.051 35.367,0.75 16.25,0.75 15,2 15,31.679 20.194,36.873 32.599,36.873 33.079,36.392 33.079,35.392 32.117,34.43 32.117,32.308 30.759,30.95 30.367,30.95 30.367,31.547 31.286,32.466 31.286,35.058 30.853,35.49 29.692,35.49 29.292,35.09 29.292,30.098 29.115,29.921 28.364,29.921 28.242,30.043 28.242,33.646 27.939,33.949 24.755,33.949 24.452,33.646 24.452,32.381 24.693,32.139 25.523,32.139 26.636,31.027 26.636,30.211 26.354,29.921 26.032,29.921 25.839,29.728 27.401,28.166 27.401,27.309 26.264,27.309 26.153,27.198 24.28,27.198 24.28,26.156 25.874,24.563 27.673,24.563 27.675,24.565 27.732,24.508 27.732,18.236 27.982,17.986
GND on Top Layer "TOP_LAYER_GND_P053" (solid, remove dead copper, pour order 53): 32.527,69.133 32.267,69.393 32.267,71.169 32.053,71.384 27.745,71.384 27.49,71.128 27.49,67.094 27.862,66.741 31.943,66.741 32.267,67.065 32.267,68.259 32.586,68.577 33.125,68.577 33.125,69.133
VOUT1_1 on Top Layer "TOP_LAYER_VOUT1_1_P051" (solid, remove dead copper, pour order 51): 83.5,87 82.401,85.901 82.401,0.75 92.873,0.75 93.129,1.006 93.129,19.973 94.907,21.75 104.997,21.75 104.997,21.355 95.096,21.355 93.522,19.781 93.522,0.987 93.759,0.75 117.1,0.75 125.219,8.869 125.219,21.974 107.538,21.974 106.5,23.012 106.5,53.727 107.321,54.548 124.345,54.548 125.219,55.281 125.219,79.281 117.5,87 93.5,87 93,86.5 93,69.058 95.437,66.621 104.997,66.621 104.997,66.238 95.319,66.238 92.651,68.907 92.651,86.599 92.25,87
GND on Top Layer "Top Layer-GND" (solid, remove dead copper, pour order 44): 39.251,43 40.001,43 45,38.001 45,2.048 43.702,0.75 40.5,0.75 39.25,2 39.251,2.001 39.251,34.608 36.667,37.192 34.1,37.192 19.815,37.192 7.874,25.25 0.507,25.25 0.507,41.672 1.835,43 29.448,43 35.575,43
VIN on Top Layer "TOP_LAYER_VIN_P008" (solid, remove dead copper, pour order 8): 41.171,43.423 41.701,43.953 41.701,51.171 40.732,52.14 31.518,52.14 31.006,51.628 31.006,43.993 31.576,43.423
GND on Top Layer "TOP_LAYER_GND_P042" (solid, remove dead copper, pour order 42): 27.714,29.582 27.475,29.343 27.475,25.176 27.794,24.858 31.924,24.858 32.262,25.196 32.262,26.373 32.669,26.779 33.124,26.779 33.124,27.198 32.587,27.198 32.262,27.523 32.262,29.179 31.859,29.582 29.445,29.582
GND on Top Layer "TOP_LAYER_GND_P025" (solid, remove dead copper, pour order 25): 80.863,5.459 80.863,1.216 80.421,0.75 61.004,0.75 60.5,1.254 60.5,13.888 61.372,14.76 63.188,14.76 63.737,14.211 63.737,7.229 65.118,5.848 80.475,5.848
GND on Top Layer "TOP_LAYER_GND_P024" (solid, remove dead copper, pour order 24): 80.863,25.875 80.863,22.781 62.147,22.781 60.5,24.428 60.5,34.387 61.02,34.908 63.358,34.908 63.737,34.529 63.737,27.408 64.706,26.439 80.299,26.439
GND on Top Layer "TOP_LAYER_GND_P023" (solid, remove dead copper, pour order 23): 80.863,46.881 80.863,44.61 79.93,43.626 61.744,43.626 60.5,44.869 60.5,55.007 61.051,55.558 63.219,55.558 63.737,55.04 63.737,48.354 64.857,47.233 80.512,47.233
GND on Top Layer "TOP_LAYER_GND_P022" (solid, remove dead copper, pour order 22): 80.863,67.301 80.863,65.571 79.324,63.947 62.122,63.947 60.5,65.569 60.5,74.849 61.372,75.721 63.188,75.721 63.737,75.173 63.737,68.191 64.216,67.711 80.453,67.711
VOUT1_1 on Top Layer "TOP_LAYER_VOUT1_1_P021" (solid, remove dead copper, pour order 21): 111.269,66 111.269,50.745 112.293,49.722 112.293,49.708 113.222,49.708 113.624,49.306 113.624,44.916 114,44.541 114,44.524 124.44,44.524 125.25,45.334 125.25,66
NetC47_1 on Top Layer "TOP_LAYER_NETC47_1_P020" (solid, remove dead copper, pour order 20): 117.75,41.85 119.22,40.38 119.22,39.827 118.984,39.591 114.276,39.591 114.276,39.624 114,39.9 114,43.785 114.276,44.061 117.487,44.061 117.75,43.798
NetL5_1 on Top Layer "TOP_LAYER_NETL5_1_P017" (solid, remove dead copper, pour order 17): 74.228,6.307 73.783,6.752 73.783,12.591 74.311,13.119 80.475,13.119 80.77,12.824 80.77,6.518 80.559,6.307
NetL3_1 on Top Layer "TOP_LAYER_NETL3_1_P016" (solid, remove dead copper, pour order 16): 74.228,27.037 73.783,27.481 73.783,33.32 74.311,33.848 80.475,33.848 80.77,33.553 80.77,27.247 80.559,27.037
NetL4_2 on Top Layer "TOP_LAYER_NETL4_2_P015" (solid, remove dead copper, pour order 15): 74.228,47.807 73.783,48.252 73.783,54.091 74.311,54.619 80.475,54.619 80.77,54.324 80.77,48.018 80.559,47.807
NetL2_2 on Top Layer "TOP_LAYER_NETL2_2_P014" (solid, remove dead copper, pour order 14): 74.228,68 73.783,68.444 73.783,74.283 74.311,74.811 80.475,74.811 80.77,74.517 80.77,68.211 80.559,68
NetC46_1 on Top Layer "TOP_LAYER_NETC46_1_P013" (solid, remove dead copper, pour order 13): 63.069,21.138 63.069,16.179 64.339,14.909 64.339,7.39 68.75,7.39 68.75,14.111 71.25,16.611 71.25,21.139 70.763,21.626 63.557,21.626
NetC38_1 on Top Layer "TOP_LAYER_NETC38_1_P012" (solid, remove dead copper, pour order 12): 63.069,41.836 63.069,37.124 64.339,35.854 64.339,28.088 68.75,28.088 68.75,34.809 71.25,37.309 71.25,41.837 70.763,42.324 63.557,42.324
NetC45_1 on Top Layer "TOP_LAYER_NETC45_1_P011" (solid, remove dead copper, pour order 11): 63.069,62.64 63.069,57.927 64.339,56.658 64.339,48.892 68.75,48.892 68.75,55.613 71.25,58.113 71.25,62.641 70.763,63.128 63.557,63.128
